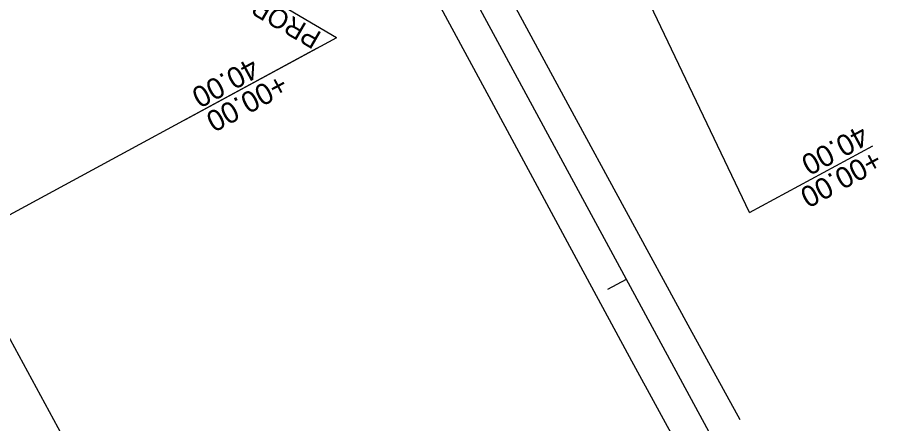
# Model space of a CAD drawing. Extents: x 1627557 to 1636561, y 783843 to 794002.
# Drawn here: x 1628143.1 to 1628393.5, y 784399.8 to 784515.8 of the extents above; entities that cross this region are included whole.
import ezdxf

# ---------------------------------------------------------------- set-up
doc = ezdxf.new("R2010")
doc.units = 0
for name, color, linetype in [('R_Horz Alg', 7, 'Continuous'), ('R_Horz Alg Annot', 7, 'Continuous'), ('R_Proposed Road', 7, 'Continuous'), ('R_ROW', 7, 'Continuous'), ('R_ROW Annot', 7, 'Continuous'), ('R_ROW Annot Labels', 7, 'Continuous'), ('R_Temp Const Easement', 7, 'Continuous'), ('R_Temp Easement Annot', 7, 'Continuous'), ('Transition Dimensions', 7, 'Continuous')]:
    doc.layers.add(name, color=color, linetype=linetype)

msp = doc.modelspace()

# ---------------------------------------------------------------- linework, layer by layer
at = {"layer": 'R_Horz Alg'}
msp.add_line((1628609.13, 783900.95), (1628236.53, 784589.68), dxfattribs=at)
at = {"layer": 'R_Horz Alg Annot'}
msp.add_lwpolyline([(1628311.67, 784438.18), (1628316.95, 784441.04)], dxfattribs=at)
at = {"layer": 'R_Proposed Road'}
for points in [[(1628277.39, 784533.33), (1628285.34, 784518.42), (1628300.76, 784489.98), (1628316.28, 784461.44), (1628335.06, 784427), (1628349.33, 784401.01)], [(1628260.85, 784524.38), (1628278.3, 784492), (1628300.03, 784451.73), (1628318.43, 784417.75), (1628332.47, 784391.89)]]:
    msp.add_lwpolyline(points, dxfattribs=at)
at = {"layer": 'R_ROW'}
msp.add_line((1628234.18, 784509.96), (1628133.89, 784569.02), dxfattribs=at)
at = {"layer": 'R_ROW Annot'}
msp.add_lwpolyline([(1628234.18, 784509.96), (1628190.97, 784486.58)], dxfattribs=at)
at = {"layer": 'R_Temp Const Easement'}
msp.add_line((1628352.13, 784460.07), (1628308.94, 784550.4), dxfattribs=at)
at = {"layer": 'R_Temp Easement Annot'}
msp.add_lwpolyline([(1628352.13, 784460.07), (1628387.31, 784479.1)], dxfattribs=at)
at = {"layer": 'Transition Dimensions'}
for p, q in [((1628228.66, 784506.97), (1628092.78, 784433.46)), ((1628197.81, 784319.04), (1628126.01, 784451.44))]:
    msp.add_line(p, q, dxfattribs=at)

# ---------------------------------------------------------------- texts
at = {"layer": 'R_ROW Annot'}
for s, p in [('40.00', (1628209.93, 784504.52)), ('+00.00', (1628218.13, 784499.87))]:
    msp.add_text(s, height=6, rotation=208.4133, dxfattribs=at).set_placement(p)
at = {"layer": 'R_ROW Annot Labels'}
msp.add_text('PROP. ROW', height=5.5, rotation=149.9112, dxfattribs=at).set_placement((1628230.21, 784511.29))
at = {"layer": 'R_Temp Easement Annot'}
for s, p in [('40.00', (1628383.98, 784485.26)), ('+00.00', (1628387.79, 784478.22))]:
    msp.add_text(s, height=6, rotation=208.4133, dxfattribs=at).set_placement(p)

doc.saveas('drawing.dxf')
